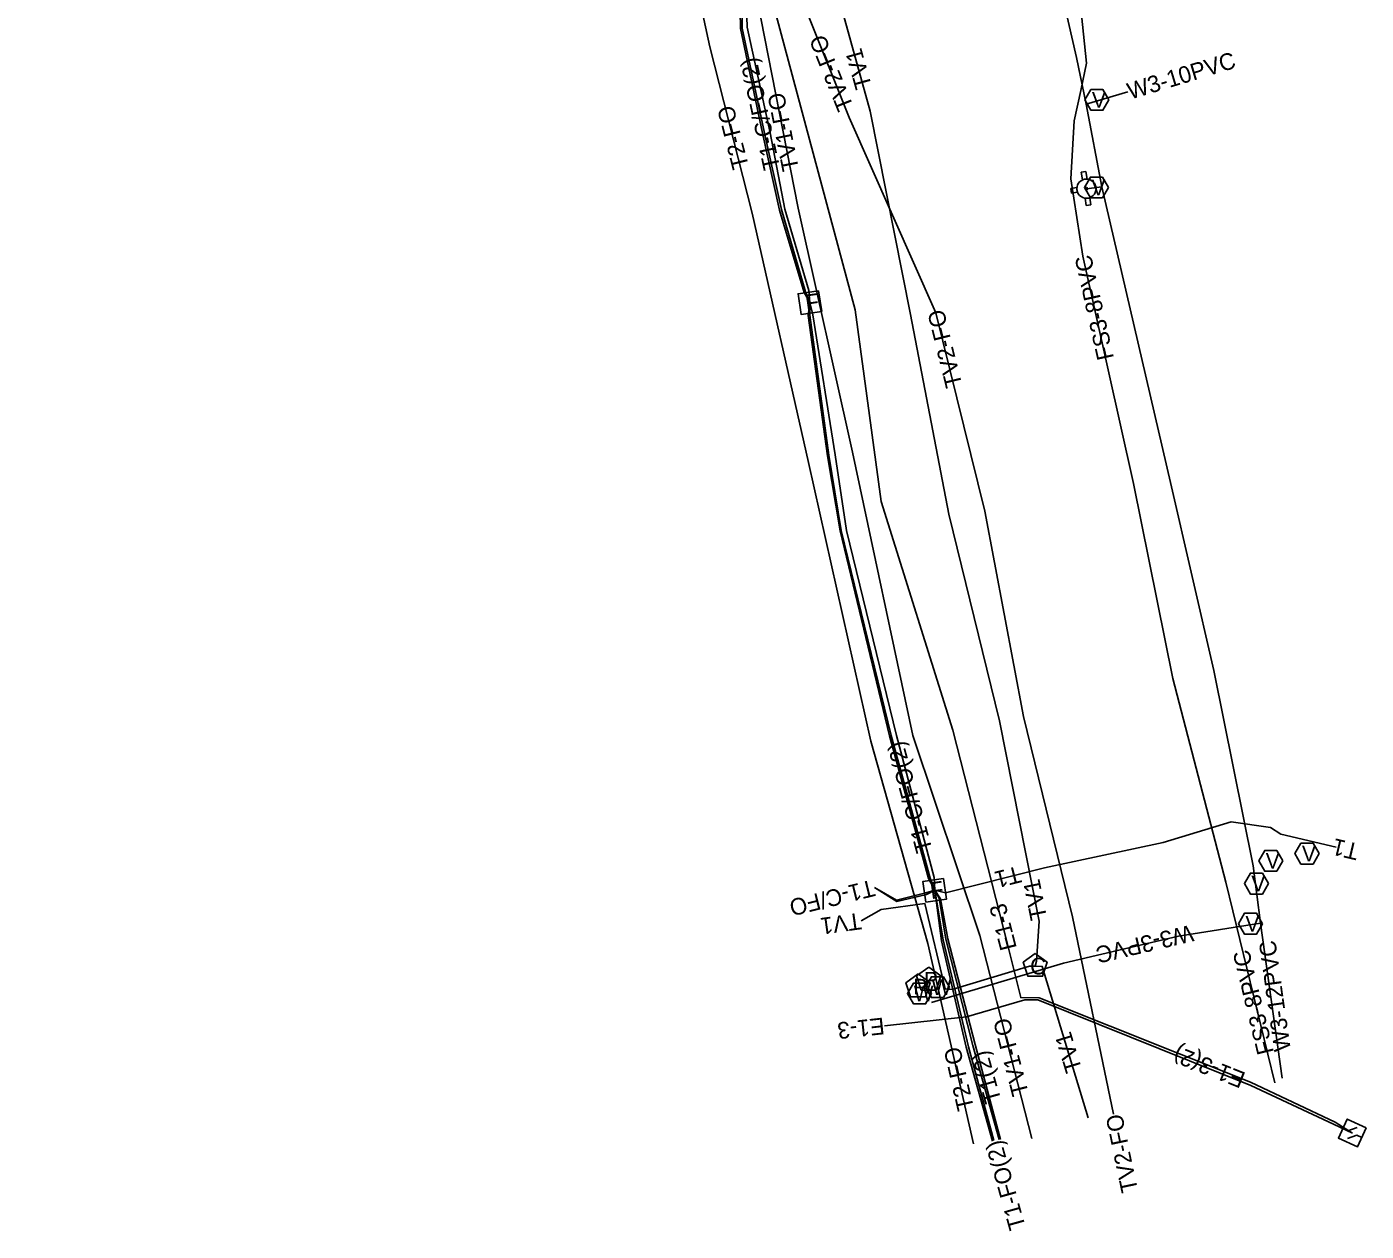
# Model space of a CAD drawing. Extents: x 2336688 to 2352634, y 362473 to 369571.
# Drawn here: x 2351107 to 2351428.1, y 368198.7 to 368487.4 of the extents above; entities that cross this region are included whole.
import ezdxf

# ---------------------------------------------------------------- set-up
doc = ezdxf.new("R2010")
doc.units = 0
for name, color, linetype in [('RD_EX_DV_Prop', 7, 'Continuous'), ('RD_EX_RW', 7, 'Continuous'), ('RD_EX_RW_TX', 7, 'Continuous'), ('RD_PD_CstnLmt', 7, 'Continuous'), ('RD_PD_Final_TrvlWay', 7, 'Continuous'), ('RD_Sketch1', 7, 'Continuous'), ('RD_Sketch2', 7, 'Continuous'), ('RD_Sketch5', 7, 'Continuous')]:
    doc.layers.add(name, color=color, linetype=linetype)

msp = doc.modelspace()

# ---------------------------------------------------------------- linework, layer by layer
at = {"layer": 'RD_EX_RW'}
for p, q in [((2351310.19, 368281.06), (2351315.57, 368277.67)), ((2351310.19, 368281.06), (2351315.49, 368278.02)), ((2351307.01, 368273.07), (2351311.79, 368275.82))]:
    msp.add_line(p, q, dxfattribs=at)
at = {"layer": 'RD_EX_RW_TX'}
for points in [[(2351229.57, 368681.2), (2351236.31, 368674.67), (2351246.71, 368656.78), (2351255.29, 368638.83), (2351261.43, 368617.85), (2351272.66, 368562.38), (2351276.62, 368537.07), (2351278.06, 368512.39), (2351278.47, 368487.08), (2351283.79, 368461.87), (2351287.88, 368443.56), (2351293.65, 368423.89), (2351294.69, 368421.28), (2351294.65, 368418.28), (2351299.27, 368384.69), (2351302.21, 368366.6), (2351314.15, 368317.48), (2351323.5, 368283.26), (2351324.62, 368280.4), (2351326.65, 368268.48), (2351332.74, 368242.9), (2351338.8, 368220.39)], [(2351229.57, 368681.2), (2351231.65, 368680.73), (2351237.02, 368675.27), (2351247.28, 368656.99), (2351257.55, 368638.99), (2351262.92, 368617.91), (2351274.68, 368562.58), (2351277.55, 368537.01), (2351278.86, 368512.21), (2351279.63, 368487.33), (2351285.21, 368461.97), (2351288.7, 368443.65), (2351294.43, 368424.15), (2351294.69, 368421.28), (2351295.38, 368418.33), (2351300.74, 368384.8), (2351303.48, 368366.6), (2351315.5, 368317.48), (2351324.47, 368283.48), (2351324.62, 368280.4), (2351326.05, 368278.31), (2351327.76, 368268.72), (2351334.33, 368243.44), (2351340.43, 368220.68)], [(2351201.7, 368675.07), (2351200.9, 368674.18), (2351199.85, 368669.59), (2351200.94, 368667.75), (2351209.33, 368659.77), (2351224.28, 368644.55), (2351248.82, 368614.72), (2351260.32, 368576.83), (2351263.86, 368573.06), (2351274.91, 368568.76), (2351278.23, 368562.48), (2351287.8, 368513.68), (2351294.26, 368490.16), (2351304.11, 368465.66), (2351324.92, 368418.83), (2351336.62, 368371.25), (2351345.89, 368322.07), (2351357.63, 368274.06), (2351367.51, 368226.74)], [(2351201.7, 368675.07), (2351202.6, 368674.93), (2351203.83, 368673.26), (2351214.84, 368664.62), (2351226.69, 368656.09), (2351242.04, 368611.12), (2351265.35, 368507.38), (2351270.72, 368482.62), (2351280.89, 368442.69), (2351294.4, 368382.92), (2351309.3, 368316.16), (2351323.01, 368267.6), (2351333.96, 368219.65)], [(2351347.88, 368220.89), (2351335.42, 368269.54), (2351319.4, 368317.47), (2351304.95, 368385.45), (2351291.9, 368443.88), (2351282.94, 368489.45), (2351270.28, 368536), (2351260.61, 368560.04), (2351253.62, 368591.72), (2351246.42, 368612.74), (2351233.68, 368651.1), (2351228.65, 368657.79), (2351212.63, 368673.18), (2351209.05, 368673.77), (2351206.87, 368673.76), (2351205.08, 368675.04), (2351201.7, 368675.07)], [(2351106.98, 368642.54), (2351108.2, 368643.82), (2351112.1, 368647.52), (2351122.3, 368650.08), (2351147.51, 368660.33), (2351168.99, 368663.71), (2351196.81, 368668.47), (2351215.57, 368666.89), (2351228.74, 368660.6), (2351236.29, 368653.23), (2351251.67, 368614.06), (2351260.37, 368594.17), (2351276.84, 368580.47), (2351283.03, 368563.52), (2351295.62, 368515.94), (2351309.17, 368467.12), (2351318.82, 368418.4), (2351327.99, 368370.54), (2351340.14, 368321.05), (2351349.7, 368273.01), (2351349.03, 368263.4), (2351348.72, 368262.22), (2351350.42, 368262.16), (2351361.39, 368225.88)], [(2351277.56, 368512.26), (2351278.05, 368486.96), (2351283.33, 368461.87), (2351287.39, 368443.46), (2351293.29, 368423.7), (2351294.69, 368421.28), (2351294.25, 368418.17), (2351298.94, 368384.55), (2351301.92, 368366.52), (2351313.79, 368317.38), (2351323.17, 368283.24), (2351324.62, 368280.4), (2351326.26, 368268.24), (2351332.17, 368242.77), (2351338.47, 368220.29)], [(2351420.89, 368290.75), (2351407.6, 368293.88), (2351405.15, 368295.46), (2351395.71, 368296.77), (2351379.41, 368291.88), (2351350.98, 368285.8), (2351327.25, 368279.78), (2351324.62, 368280.4), (2351322.52, 368279.75), (2351315.49, 368278.02)], [(2351324.62, 368280.4), (2351322.62, 368279.4), (2351315.57, 368277.67)], [(2351324.62, 368280.4), (2351325.69, 368278.49), (2351327.32, 368268.64), (2351333.78, 368243.22), (2351340.05, 368220.63)], [(2351311.79, 368275.82), (2351322.24, 368277.26), (2351327.17, 368256.77), (2351328.8, 368256.63), (2351347.38, 368262.22), (2351348.72, 368262.22)]]:
    msp.add_lwpolyline(points, dxfattribs=at)
for points in [[(2351296.8, 368424.12), (2351291.86, 368423.39), (2351292.59, 368418.44), (2351297.53, 368419.17)], [(2351326.72, 368283.24), (2351321.78, 368282.51), (2351322.51, 368277.56), (2351327.46, 368278.3)], [(2351348.72, 368265.22), (2351345.86, 368263.15), (2351346.95, 368259.79), (2351350.48, 368259.79), (2351351.57, 368263.15)]]:
    msp.add_lwpolyline(points, close=True, dxfattribs=at)
at = {"layer": 'RD_PD_Final_TrvlWay'}
for points in [[(2351201.7, 368675.07), (2351203.2, 368677.17), (2351207.26, 368685.59), (2351212.59, 368690.14), (2351215.83, 368690.95), (2351229.23, 368694.57), (2351236.84, 368689.03), (2351245.47, 368675.57), (2351251.27, 368659.04), (2351260.11, 368617.75), (2351265.77, 368594.9), (2351274.15, 368562.38), (2351274.64, 368537), (2351280.71, 368512.32), (2351305.52, 368419.51), (2351311.8, 368373.58), (2351328.95, 368318.81), (2351342.04, 368267.45), (2351345.25, 368254.66), (2351349.65, 368254.61), (2351400.34, 368234.37), (2351420.6, 368224.79), (2351424.74, 368222.21)], [(2351424.74, 368222.21), (2351420.19, 368224.32), (2351400.37, 368233.58), (2351349.38, 368254.1), (2351346.23, 368254.17), (2351332.27, 368250.05), (2351312.61, 368247.91)], [(2351422.48, 368223.27), (2351423.68, 368222.71), (2351425.93, 368223.52)], [(2351427.01, 368221.16), (2351425.8, 368221.72), (2351423.55, 368220.9)]]:
    msp.add_lwpolyline(points, dxfattribs=at)
msp.add_lwpolyline([(2351428.06, 368223.42), (2351423.53, 368225.54), (2351421.42, 368221.01), (2351425.95, 368218.89)], close=True, dxfattribs=at)
at = {"layer": 'RD_Sketch2'}
for p, q in [((2351360.92, 368468.8), (2351370.93, 368471.82)), ((2351360.89, 368452.68), (2351359.75, 368452.51)), ((2351359.75, 368452.51), (2351360.02, 368450.67)), ((2351361.16, 368450.88), (2351360.89, 368452.68)), ((2351358.71, 368448.87), (2351357.23, 368448.65)), ((2351357.23, 368448.65), (2351357.4, 368447.51)), ((2351361, 368448.58), (2351364.7, 368449.04)), ((2351357.4, 368447.51), (2351358.86, 368447.73)), ((2351360.67, 368446.29), (2351360.94, 368444.51)), ((2351362.08, 368444.68), (2351361.82, 368446.42)), ((2351360.94, 368444.51), (2351362.08, 368444.68))]:
    msp.add_line(p, q, dxfattribs=at)
for points in [[(2351291.49, 368752.07), (2351292.44, 368749.67), (2351314.26, 368673.05), (2351321.83, 368640.92), (2351324.93, 368624.92), (2351336.6, 368573.65), (2351350, 368517.73), (2351358.62, 368479.99), (2351360.92, 368468.8), (2351364.7, 368449.04), (2351381.15, 368378.14), (2351391.51, 368333.08), (2351400.94, 368286.23), (2351402.7, 368272.49), (2351407.94, 368235.33)], [(2351291.49, 368752.07), (2351292.44, 368749.67), (2351314.26, 368673.05), (2351321.83, 368640.92), (2351324.93, 368624.92), (2351336.6, 368573.65), (2351350, 368517.73), (2351358.62, 368479.99), (2351360.92, 368468.8), (2351364.7, 368449.04), (2351381.15, 368378.14), (2351391.51, 368333.08), (2351400.94, 368286.23), (2351402.7, 368272.49), (2351407.94, 368235.33)], [(2351323.82, 368253.49), (2351355.51, 368262.92), (2351383.04, 368269.39), (2351402.7, 368272.49)]]:
    msp.add_lwpolyline(points, dxfattribs=at)
for points in [[(2351366.4, 368469.86), (2351364.96, 368472.35), (2351362.07, 368472.35), (2351360.63, 368469.86), (2351362.07, 368467.36), (2351364.96, 368467.36)], [(2351366.29, 368448.86), (2351364.84, 368451.36), (2351361.96, 368451.36), (2351360.51, 368448.86), (2351361.96, 368446.36), (2351364.84, 368446.36)], [(2351416.76, 368289.18), (2351415.32, 368291.68), (2351412.43, 368291.68), (2351410.99, 368289.18), (2351412.43, 368286.68), (2351415.32, 368286.68)], [(2351408.07, 368287.46), (2351406.62, 368289.96), (2351403.74, 368289.96), (2351402.29, 368287.46), (2351403.74, 368284.96), (2351406.62, 368284.96)], [(2351404.62, 368282), (2351403.18, 368284.5), (2351400.29, 368284.5), (2351398.85, 368282), (2351400.29, 368279.5), (2351403.18, 368279.5)], [(2351403.21, 368272.38), (2351401.77, 368274.87), (2351398.88, 368274.87), (2351397.44, 368272.38), (2351398.88, 368269.88), (2351401.77, 368269.88)], [(2351323.19, 368262), (2351320.29, 368259.89), (2351321.39, 368256.48), (2351324.98, 368256.48), (2351326.09, 368259.89)], [(2351320.63, 368260.34), (2351317.73, 368258.23), (2351318.84, 368254.82), (2351322.43, 368254.82), (2351323.53, 368258.23)], [(2351328.17, 368257.18), (2351326.73, 368259.68), (2351323.84, 368259.68), (2351322.4, 368257.18), (2351323.84, 368254.68), (2351326.73, 368254.68)], [(2351323.88, 368255.66), (2351322.43, 368258.16), (2351319.55, 368258.16), (2351318.1, 368255.66), (2351319.55, 368253.16), (2351322.43, 368253.16)]]:
    msp.add_lwpolyline(points, close=True, dxfattribs=at)
for radius in [2.31, 0.289]:
    msp.add_circle((2351361, 368448.58), radius, dxfattribs=at)
for start, end in [(172.6694, 201.6366), (86.1089, 115.0852), (261.7626, 290.7389)]:
    msp.add_arc((2351361, 368448.58), 2.31, start, end, dxfattribs=at)
at = {"layer": 'RD_Sketch5'}
msp.add_lwpolyline([(2351305.9, 368740.94), (2351311.36, 368724.83), (2351314.62, 368712.79), (2351315.62, 368708.28), (2351322.75, 368677.68), (2351334.79, 368627.22), (2351346.13, 368578.21), (2351355.63, 368530.54), (2351360.98, 368478.66), (2351359.66, 368472.12), (2351358.04, 368464.88), (2351357.27, 368450.93), (2351360.12, 368432.44), (2351372.24, 368377.88), (2351381.74, 368331.13), (2351394.45, 368282.37), (2351406.13, 368234.27)], dxfattribs=at)

# ---------------------------------------------------------------- texts
at = {"layer": 'RD_EX_DV_Prop'}
for s, rotation, p in [('E1-3', 104.3045, (2351344.33, 368266.59)), ('E1-3', 186.2036, (2351312.36, 368249.9)), ('E1-3(2)', 158.2323, (2351399.41, 368236.55))]:
    msp.add_text(s, height=4, rotation=rotation, dxfattribs=at).set_placement(p)
at = {"layer": 'RD_EX_RW'}
for s, rotation, p in [('TV2-FO', 111.8997, (2351305.24, 368468.21)), ('TV1', 105.5083, (2351309.59, 368473.08)), ('T1-C/FO(2)', 102.1206, (2351287.59, 368453.57)), ('TV1-FO', 101.1326, (2351292.11, 368453.22)), ('T2-FO', 104.2912, (2351280.12, 368453.84)), ('TV2-FO', 103.8113, (2351331.26, 368401.44)), ('T1-C/FO(2)', 105.1104, (2351324.15, 368290.04)), ('T1', 166.7371, (2351426.61, 368291.45)), ('T1', 194.2259, (2351344.73, 368286.28)), ('T1-C/FO', 193.8116, (2351309.68, 368282.99)), ('TV1', 101.2579, (2351351.6, 368273.69)), ('TV1', 187.8472, (2351306.74, 368275.05)), ('TV1-FO', 104.3622, (2351347.18, 368231.67)), ('TV1', 106.8168, (2351359.99, 368237.41)), ('T2-FO', 102.86, (2351334.08, 368228.09)), ('T1(2)', 105.499, (2351340.63, 368229.97)), ('TV2-FO', 101.7892, (2351373.38, 368208.41)), ('T1-FO(2)', 105.6508, (2351346.48, 368199.63))]:
    msp.add_text(s, height=4, rotation=rotation, dxfattribs=at).set_placement(p)
at = {"layer": 'RD_EX_RW_TX'}
for p in [(2351293.87, 368419.13), (2351323.79, 368278.26)]:
    msp.add_text('F', height=4, rotation=8.4239, dxfattribs=at).set_placement(p)
msp.add_text('C', height=4, dxfattribs=at).set_placement((2351347.49, 368260.22))
at = {"layer": 'RD_PD_CstnLmt'}
for s, rotation, p in [('W3-10PVC', 16.8005, (2351371.51, 368469.91)), ('W3-3PVC', 193.2092, (2351386.07, 368272.15)), ('W3-12PVC', 98.0288, (2351410.01, 368242.09))]:
    msp.add_text(s, height=4, rotation=rotation, dxfattribs=at).set_placement(p)
at = {"layer": 'RD_Sketch1'}
for rotation, p in [(102.5299, (2351367.6, 368408)), (103.6407, (2351405.96, 368241.56))]:
    msp.add_text('FS3-8PVC', height=4, rotation=rotation, dxfattribs=at).set_placement(p)
at = {"layer": 'RD_Sketch2'}
for s, p in [('V', (2351362.31, 368467.98)), ('V', (2351362.19, 368446.98)), ('V', (2351412.66, 368287.3)), ('V', (2351403.97, 368285.59)), ('V', (2351400.52, 368280.13)), ('V', (2351399.11, 368270.5)), ('W', (2351323.89, 368255.31)), ('W', (2351319.6, 368253.79))]:
    msp.add_text(s, height=3.75, dxfattribs=at).set_placement(p)
for p in [(2351319.48, 368255.42), (2351322.04, 368257.08)]:
    msp.add_text('P', height=3.75, rotation=360, dxfattribs=at).set_placement(p)

doc.saveas('drawing.dxf')
